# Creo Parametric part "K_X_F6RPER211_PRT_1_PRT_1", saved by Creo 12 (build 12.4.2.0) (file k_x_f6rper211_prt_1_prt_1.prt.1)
Units: Custom; MM, KILOGRAM, SECS

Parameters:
  PTC_WM_ITERATION = "0"
  PTC_WM_VERSION = "-.0"
  PTC_WM_LIFECYCLE_STATE = "In Work"
  PTC_WM_LIFECYCLE = "MO_CADDocument"
  PTC_WM_CREATED_BY = "Maximilian Roepper (Z0017RMS: MO)"
  PTC_WM_CREATED_ON = "18-Sep-26 11:36:42 AM"
  PTC_WM_MODIFIED_BY = "Maximilian Roepper (Z0017RMS: MO)"
  PTC_WM_MODIFIED_ON = "18-Sep-26 11:36:46 AM"
  PDMLINKNUMBER = "PDM000071455091"
  PTC_WM_NAME = "k_x_f6rper211_prt_1_prt_1.prt"
  PTC_WM_NUMBER = "PDM000071455091"

Other parameters: WEIGHT, WEIGHT_FACTOR, WEIGHT_ADD, _MASS_TEMP, _DIFF_TEMP, MC_ERRORS, SUPPLIER

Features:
  1. coordinate system
  2. datum plane "PRT_YZ"
  3. datum plane "PRT_XY"
  4. datum plane "PRT_XZ"
  5. coordinate system
  6. datum axis
  7. datum axis
  8. datum axis
  9. coordinate system
  10. imported feature
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
Other named items: PRT, SIEMENS_MO, DRW_VIEW_ORG, PRT_X, PRT_Y, PRT_Z, CS0, ROUGH_GROB

Layers: 00_STD_CSYS-KSYS, 01_STD_PLANES-EBENEN, 02_STD_AXES-ACHSEN, 03_STD_CSYS-KSYS, 24_IMPORT_FEAT-IMPORT_KE

Surfaces: 15 tabulated cylinder, 9 plane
